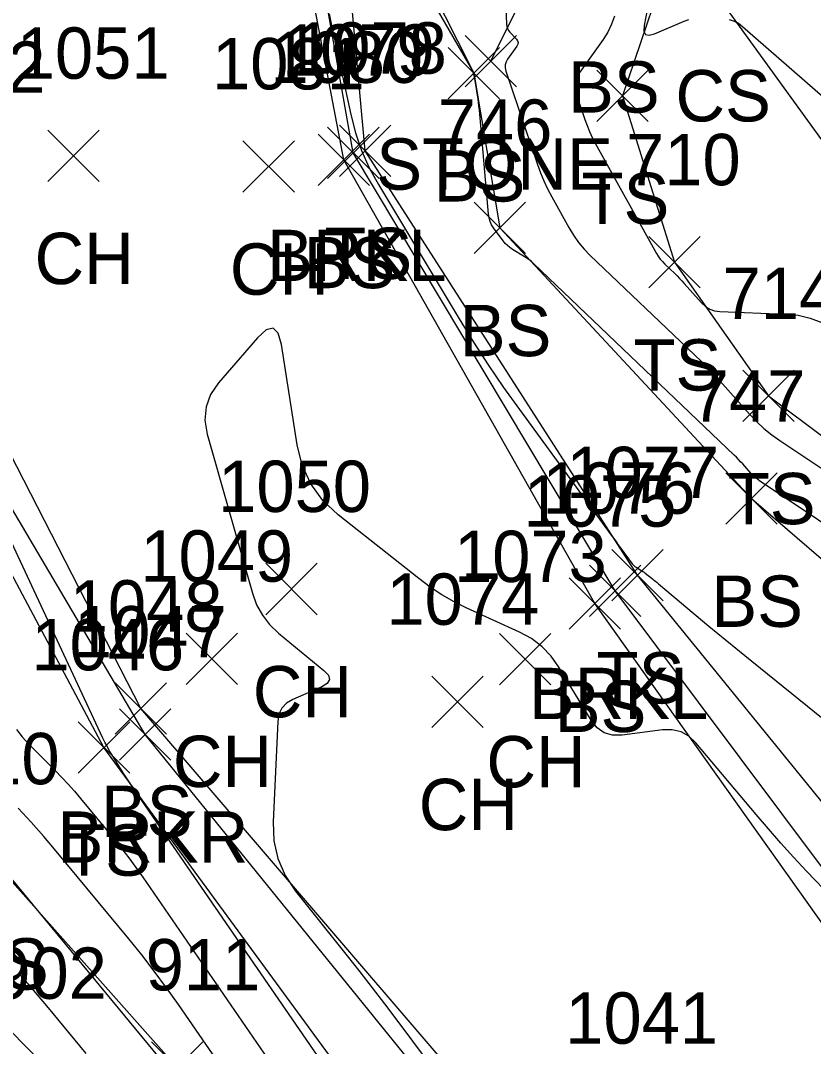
# Model space of a CAD drawing. Extents: x 1592612 to 1596497, y 111838 to 113741.
# Drawn here: x 1592839.94 to 1592870.82, y 113483.39 to 113523.36 of the extents above; entities that cross this region are included whole.
import ezdxf

# ---------------------------------------------------------------- set-up
doc = ezdxf.new("R2010")
doc.units = 0
for name, color, linetype in [('L_A', 7, 'Continuous'), ('L_I', 7, 'Continuous'), ('L_TIC', 7, 'Continuous'), ('LASF', 7, 'Continuous'), ('LAWE', 7, 'Continuous'), ('LELB', 7, 'Continuous'), ('LSOGCMA', 7, 'Continuous'), ('LSOGCMI', 7, 'Continuous')]:
    doc.layers.add(name, color=color, linetype=linetype)

msp = doc.modelspace()

# ---------------------------------------------------------------- linework, layer by layer
at = {"layer": 'L_TIC'}
for points in [[(1592857.251, 113520.771), (1592859.251, 113522.771)], [(1592859.251, 113520.771), (1592857.251, 113522.771)], [(1592857.251, 113520.771), (1592859.251, 113522.771)], [(1592859.251, 113520.771), (1592857.251, 113522.771)], [(1592856.59, 113520.31), (1592858.59, 113522.31)], [(1592858.59, 113520.31), (1592856.59, 113522.31)], [(1592862.38, 113519.43), (1592864.38, 113521.43)], [(1592864.38, 113519.43), (1592862.38, 113521.43)], [(1592841.001, 113517.092), (1592843.001, 113519.092)], [(1592843.001, 113517.092), (1592841.001, 113519.092)], [(1592851.902, 113517.209), (1592853.902, 113519.209)], [(1592853.902, 113517.209), (1592851.902, 113519.209)], [(1592852.365, 113517.29), (1592854.365, 113519.29)], [(1592854.365, 113517.29), (1592852.365, 113519.29)], [(1592848.605, 113516.678), (1592850.605, 113518.678)], [(1592850.605, 113516.678), (1592848.605, 113518.678)], [(1592851.529, 113516.932), (1592853.529, 113518.932)], [(1592853.529, 113516.932), (1592851.529, 113518.932)], [(1592857.606, 113514.284), (1592859.606, 113516.284)], [(1592859.606, 113514.284), (1592857.606, 113516.284)], [(1592864.405, 113512.944), (1592866.405, 113514.944)], [(1592866.405, 113512.944), (1592864.405, 113514.944)], [(1592868.075, 113507.737), (1592870.075, 113509.737)], [(1592870.075, 113507.737), (1592868.075, 113509.737)], [(1592867.403, 113503.739), (1592869.403, 113505.739)], [(1592869.403, 113503.739), (1592867.403, 113505.739)], [(1592862.966, 113500.755), (1592864.966, 113502.755)], [(1592864.966, 113500.755), (1592862.966, 113502.755)], [(1592849.498, 113500.214), (1592851.498, 113502.214)], [(1592851.498, 113500.214), (1592849.498, 113502.214)], [(1592862.095, 113500.144), (1592864.095, 113502.144)], [(1592864.095, 113500.144), (1592862.095, 113502.144)], [(1592861.304, 113499.643), (1592863.304, 113501.643)], [(1592863.304, 113499.643), (1592861.304, 113501.643)], [(1592846.387, 113497.499), (1592848.387, 113499.499)], [(1592848.387, 113497.499), (1592846.387, 113499.499)], [(1592858.594, 113497.485), (1592860.594, 113499.485)], [(1592860.594, 113497.485), (1592858.594, 113499.485)], [(1592855.961, 113495.819), (1592857.961, 113497.819)], [(1592857.961, 113495.819), (1592855.961, 113497.819)], [(1592843.631, 113495.556), (1592845.631, 113497.556)], [(1592845.631, 113495.556), (1592843.631, 113497.556)], [(1592843.793, 113494.549), (1592845.793, 113496.549)], [(1592845.793, 113494.549), (1592843.793, 113496.549)], [(1592842.193, 113494.045), (1592844.193, 113496.045)], [(1592844.193, 113494.045), (1592842.193, 113496.045)], [(1592845.044, 113481.577), (1592847.044, 113483.577)], [(1592847.044, 113481.577), (1592845.044, 113483.577)]]:
    msp.add_lwpolyline(points, dxfattribs=at)
at = {"layer": 'LASF'}
msp.add_lwpolyline([(1592858.251, 113521.771), (1592862.894, 113531.12), (1592866.6, 113537.992), (1592860.296, 113546.413), (1592853.331, 113544.545), (1592851.058, 113542.555)], dxfattribs=at)
at = {"layer": 'LAWE'}
for points in [[(1592886.537, 113460.922), (1592877.744, 113481.574), (1592863.095, 113501.144), (1592852.902, 113518.209), (1592848.805, 113541.382), (1592835.879, 113571.623), (1592826.212, 113589.998), (1592821.08, 113603.103), (1592811.502, 113625.047), (1592801.909, 113656.496), (1592787.746, 113677.481), (1592769.551, 113701.793), (1592752.509, 113717.946)], [(1592867.645, 113460.38), (1592859.409, 113477.515), (1592844.793, 113495.549), (1592832.37, 113516.6), (1592826.928, 113530.545), (1592818.762, 113547.936), (1592807.597, 113581.108), (1592797.669, 113603.177), (1592787.513, 113626.88), (1592776.477, 113646.362), (1592766.38, 113665.342), (1592748.736, 113682.085), (1592730.356, 113695.945)]]:
    msp.add_lwpolyline(points, dxfattribs=at)
at = {"layer": 'LELB'}
for points in [[(1592886.583, 113460.952), (1592879.778, 113482.315), (1592863.966, 113501.755), (1592853.366, 113518.29), (1592851.192, 113542.037), (1592841.019, 113567.093), (1592831.516, 113591.894), (1592821.816, 113602.808), (1592813.329, 113624.79), (1592804.232, 113657.067), (1592789.644, 113678.369), (1592770.935, 113703.549), (1592752.623, 113718.428)], [(1592886.43, 113460.851), (1592879.543, 113465.926), (1592876.137, 113481.194), (1592862.304, 113500.643), (1592852.529, 113517.932), (1592848.162, 113540.894), (1592835.177, 113571.255), (1592825.196, 113589.927), (1592820.421, 113603.303), (1592810.027, 113625.391), (1592799.468, 113655.332), (1592786.607, 113676.744), (1592768.899, 113700.806), (1592752.213, 113717.027)], [(1592869.098, 113460.398), (1592860.441, 113478.115), (1592844.631, 113496.556), (1592834.165, 113516.964), (1592828.396, 113531.171), (1592823.559, 113549.918), (1592808.456, 113581.723), (1592799.527, 113603.061), (1592789.48, 113627.849), (1592777.21, 113647.427), (1592766.461, 113666.146), (1592749.422, 113683.288), (1592730.933, 113697.021)], [(1592856.492, 113476.867), (1592843.193, 113495.045), (1592831.688, 113516.664), (1592823.204, 113528.692), (1592814.853, 113545.459), (1592806.797, 113580.845), (1592796.452, 113601.854), (1592785.293, 113626.354), (1592775.723, 113645.654), (1592766.309, 113664.453), (1592745.043, 113679.184), (1592727.847, 113694.217)], [(1592885.411, 113547.376), (1592876.234, 113539.25), (1592867.617, 113532.911), (1592863.38, 113520.43), (1592865.405, 113513.944), (1592869.075, 113508.737), (1592880.629, 113500.08), (1592889.409, 113493.364), (1592892.469, 113484.552), (1592893.995, 113472.176), (1592892.484, 113467.779), (1592891.718, 113461.24)], [(1592853.127, 113529.053), (1592857.59, 113521.31), (1592858.606, 113515.284), (1592868.403, 113504.739), (1592877.011, 113497.321), (1592880.268, 113489.72), (1592885.949, 113485.322), (1592886.296, 113475.852), (1592890.02, 113471.216), (1592888.879, 113464.325)], [(1592867.005, 113524.43), (1592872.973, 113516.163), (1592876.794, 113505.866)], [(1592852.772, 113465.837), (1592843.246, 113475.946), (1592841.284, 113482.249), (1592834.613, 113489.001), (1592825.295, 113491.22), (1592825.335, 113498.762), (1592820.851, 113504.775)], [(1592825.629, 113501.489), (1592831.446, 113497.285), (1592838.885, 113490.608), (1592846.044, 113482.577), (1592850.995, 113476.269), (1592857.832, 113468.308), (1592859.25, 113463.159)]]:
    msp.add_lwpolyline(points, dxfattribs=at)
at = {"layer": 'LSOGCMA'}
for points in [[(1592858.659, 113528.415), (1592858.873, 113523.217), (1592858.884, 113523.13), (1592858.909, 113523.049), (1592858.949, 113522.974), (1592859.003, 113522.904), (1592859.25, 113522.64), (1592859.297, 113522.573), (1592859.316, 113522.504), (1592859.306, 113522.433), (1592859.268, 113522.36), (1592858.91, 113521.856), (1592858.848, 113521.745), (1592858.816, 113521.63), (1592858.813, 113521.511), (1592858.841, 113521.387), (1592860.07, 113517.753), (1592860.187, 113517.43), (1592860.319, 113517.113), (1592860.465, 113516.802), (1592860.626, 113516.497), (1592861.295, 113515.291), (1592861.473, 113514.997), (1592861.671, 113514.719), (1592861.89, 113514.458), (1592862.129, 113514.211), (1592866.187, 113510.337), (1592866.469, 113510.061), (1592866.746, 113509.78), (1592867.017, 113509.494), (1592867.282, 113509.202), (1592868.331, 113508.023), (1592868.602, 113507.737), (1592868.889, 113507.471), (1592869.193, 113507.224), (1592869.513, 113506.995), (1592878.54, 113500.973)], [(1592847.959, 113482.309), (1592846.09, 113485.027), (1592845.629, 113485.682), (1592845.153, 113486.327), (1592844.664, 113486.962), (1592844.16, 113487.586), (1592841.336, 113491.007), (1592840.855, 113491.576), (1592840.362, 113492.133), (1592839.855, 113492.679)]]:
    msp.add_lwpolyline(points, dxfattribs=at)
at = {"layer": 'LSOGCMI'}
for points in [[(1592865.072, 113527.575), (1592864.231, 113523.173), (1592864.218, 113522.95), (1592864.281, 113522.822), (1592864.419, 113522.787), (1592864.634, 113522.847), (1592865.784, 113523.333), (1592865.97, 113523.4)], [(1592871.184, 113503.781), (1592870.809, 113504.038), (1592868.738, 113505.42), (1592868.641, 113505.489), (1592868.55, 113505.563), (1592868.463, 113505.644), (1592868.381, 113505.73), (1592868.065, 113506.086), (1592867.985, 113506.174), (1592867.903, 113506.261), (1592867.819, 113506.346), (1592867.734, 113506.429), (1592859.927, 113513.884), (1592859.835, 113513.968), (1592859.738, 113514.046), (1592859.637, 113514.119), (1592859.531, 113514.186), (1592859.102, 113514.445), (1592858.998, 113514.514), (1592858.904, 113514.593), (1592858.817, 113514.68), (1592858.739, 113514.777), (1592858.366, 113515.284), (1592858.288, 113515.406), (1592858.229, 113515.535), (1592858.189, 113515.671), (1592858.167, 113515.814), (1592857.809, 113519.873), (1592857.795, 113520.018), (1592857.778, 113520.163), (1592857.759, 113520.308), (1592857.737, 113520.452), (1592857.646, 113521.029), (1592857.618, 113521.171), (1592857.579, 113521.31), (1592857.529, 113521.446), (1592857.469, 113521.578), (1592855.51, 113525.46)], [(1592851.959, 113523.619), (1592852.057, 113523.173), (1592852.8, 113519.701), (1592852.984, 113518.985), (1592853.225, 113518.291), (1592853.523, 113517.619), (1592853.878, 113516.97), (1592857.025, 113511.733), (1592857.581, 113510.831), (1592858.157, 113509.943), (1592858.752, 113509.068), (1592859.368, 113508.206), (1592862.945, 113503.314), (1592863.033, 113503.194), (1592863.12, 113503.074), (1592863.208, 113502.954), (1592863.296, 113502.835), (1592863.76, 113502.201), (1592863.793, 113502.161), (1592863.829, 113502.124), (1592863.869, 113502.092), (1592863.912, 113502.063), (1592864.092, 113501.954), (1592864.137, 113501.927), (1592864.18, 113501.897), (1592864.223, 113501.867), (1592864.264, 113501.835), (1592864.547, 113501.612), (1592864.608, 113501.564), (1592864.668, 113501.515), (1592864.728, 113501.466), (1592864.788, 113501.416), (1592866.747, 113499.772), (1592867.094, 113499.482), (1592867.442, 113499.194), (1592867.792, 113498.907), (1592868.143, 113498.622), (1592879.061, 113489.793)], [(1592863.074, 113523.531), (1592862.959, 113523.214), (1592862.81, 113522.912), (1592862.627, 113522.624), (1592861.723, 113521.351), (1592861.605, 113521.141), (1592861.544, 113520.923), (1592861.54, 113520.696), (1592861.592, 113520.461), (1592861.916, 113519.504), (1592862.002, 113519.267), (1592862.098, 113519.035), (1592862.205, 113518.807), (1592862.323, 113518.584), (1592864.708, 113514.289), (1592864.776, 113514.175), (1592864.853, 113514.068), (1592864.938, 113513.967), (1592865.03, 113513.871), (1592865.416, 113513.503), (1592865.511, 113513.41), (1592865.605, 113513.315), (1592865.696, 113513.219), (1592865.786, 113513.12), (1592866.463, 113512.359), (1592866.614, 113512.218), (1592866.783, 113512.115), (1592866.97, 113512.05), (1592867.176, 113512.023), (1592869.734, 113511.926), (1592870.222, 113511.876), (1592870.691, 113511.765), (1592871.142, 113511.593)], [(1592867.544, 113523.394), (1592867.726, 113523.337), (1592867.895, 113523.251), (1592868.052, 113523.134), (1592873.718, 113518.191)], [(1592873.542, 113487.099), (1592870.555, 113490.226), (1592870.049, 113490.764), (1592869.551, 113491.311), (1592869.063, 113491.865), (1592868.583, 113492.427), (1592866.242, 113495.216), (1592865.969, 113495.476), (1592865.662, 113495.647), (1592865.319, 113495.73), (1592864.943, 113495.723), (1592863.366, 113495.521), (1592862.995, 113495.519), (1592862.671, 113495.614), (1592862.395, 113495.808), (1592862.165, 113496.098), (1592860.905, 113498.169), (1592860.6, 113498.598), (1592860.243, 113498.968), (1592859.834, 113499.28), (1592859.373, 113499.533), (1592857.326, 113500.471), (1592856.831, 113500.716), (1592856.353, 113500.989), (1592855.892, 113501.29), (1592855.449, 113501.619), (1592852.312, 113504.097), (1592851.711, 113504.664), (1592851.244, 113505.309), (1592850.912, 113506.032), (1592850.712, 113506.834), (1592850.099, 113510.737), (1592849.973, 113511.183), (1592849.775, 113511.376), (1592849.505, 113511.316), (1592849.164, 113511.003), (1592847.653, 113509.246), (1592847.342, 113508.792), (1592847.165, 113508.308), (1592847.122, 113507.795), (1592847.213, 113507.252), (1592848.973, 113501.047), (1592849.136, 113500.6), (1592849.359, 113500.193), (1592849.643, 113499.825), (1592849.987, 113499.497), (1592851.76, 113498.038), (1592851.932, 113497.853), (1592851.975, 113497.685), (1592851.888, 113497.535), (1592851.671, 113497.404), (1592850.546, 113496.915), (1592850.298, 113496.77), (1592850.117, 113496.578), (1592850.003, 113496.341), (1592849.956, 113496.058), (1592849.78, 113492.14), (1592849.809, 113491.405), (1592849.964, 113490.711), (1592850.246, 113490.058), (1592850.653, 113489.446), (1592852.662, 113486.922), (1592853.152, 113486.302), (1592853.636, 113485.678), (1592854.115, 113485.051), (1592854.59, 113484.42), (1592858.822, 113478.745)], [(1592855.161, 113477.716), (1592844.27, 113493.555), (1592844.168, 113493.704), (1592844.068, 113493.855), (1592843.97, 113494.007), (1592843.874, 113494.159), (1592843.492, 113494.773), (1592843.399, 113494.927), (1592843.311, 113495.085), (1592843.227, 113495.244), (1592843.148, 113495.407), (1592836.997, 113508.58)], [(1592839.781, 113495.739), (1592840.005, 113495.452), (1592840.252, 113495.183), (1592841.29, 113494.141), (1592841.546, 113493.877), (1592841.796, 113493.608), (1592842.039, 113493.333), (1592842.277, 113493.053), (1592843.583, 113491.47), (1592843.874, 113491.109), (1592844.158, 113490.742), (1592844.433, 113490.368), (1592844.7, 113489.989), (1592851.56, 113480.013)], [(1592845.598, 113482.645), (1592841.421, 113487.718), (1592841.176, 113488.015), (1592840.931, 113488.313), (1592840.685, 113488.611), (1592840.44, 113488.908), (1592839.458, 113490.098)], [(1592842.499, 113483.115), (1592840.966, 113484.976), (1592840.606, 113485.407), (1592840.237, 113485.83), (1592839.862, 113486.247)]]:
    msp.add_lwpolyline(points, dxfattribs=at)

# ---------------------------------------------------------------- texts
at = {"layer": 'L_A'}
for s, p in [('BS', (1592861.263, 113519.774)), ('CS', (1592865.446, 113519.43)), ('STONE', (1592853.795, 113516.771)), ('BS', (1592856.031, 113516.31)), ('TS', (1592861.79, 113515.43)), ('CH', (1592840.49, 113513.092)), ('BRKL', (1592849.547, 113513.209)), ('TS', (1592851.775, 113513.29)), ('CH', (1592848.093, 113512.678)), ('BS', (1592850.97, 113512.932)), ('BS', (1592857.047, 113510.284)), ('TS', (1592863.814, 113508.944)), ('TS', (1592867.485, 113503.737)), ('BS', (1592866.844, 113499.739)), ('TS', (1592862.375, 113496.755)), ('CH', (1592848.986, 113496.214)), ('BRKL', (1592859.74, 113496.144)), ('BS', (1592860.745, 113495.643)), ('CH', (1592845.876, 113493.499)), ('CH', (1592858.082, 113493.485)), ('CH', (1592855.449, 113491.819)), ('BS', (1592843.071, 113491.556)), ('BRKR', (1592841.383, 113490.549)), ('TS', (1592841.602, 113490.045)), ('CS', (1592837.326, 113485.608))]:
    msp.add_text(s, height=2, dxfattribs=at).set_placement(p)
at = {"layer": 'L_I'}
for s, p in [('1051', (1592839.797, 113521.092)), ('1079', (1592850.122, 113521.209)), ('1078', (1592850.594, 113521.29)), ('1081', (1592847.4, 113520.678)), ('1080', (1592849.671, 113520.932)), ('1052', (1592834.966, 113520.544)), ('746', (1592856.189, 113518.284)), ('710', (1592863.523, 113516.944)), ('714', (1592867.28, 113511.737)), ('747', (1592866.041, 113507.739)), ('1077', (1592861.194, 113504.755)), ('1050', (1592847.64, 113504.214)), ('1076', (1592860.268, 113504.144)), ('1075', (1592859.532, 113503.643)), ('1049', (1592844.608, 113501.499)), ('1073', (1592856.822, 113501.485)), ('1074', (1592854.19, 113499.819)), ('1048', (1592841.859, 113499.556)), ('1047', (1592842.021, 113498.549)), ('1046', (1592840.366, 113498.045)), ('910', (1592837.003, 113493.608)), ('911', (1592844.816, 113485.577)), ('902', (1592838.843, 113485.249)), ('1041', (1592861.155, 113483.498))]:
    msp.add_text(s, height=2, dxfattribs=at).set_placement(p)

doc.saveas('drawing.dxf')
